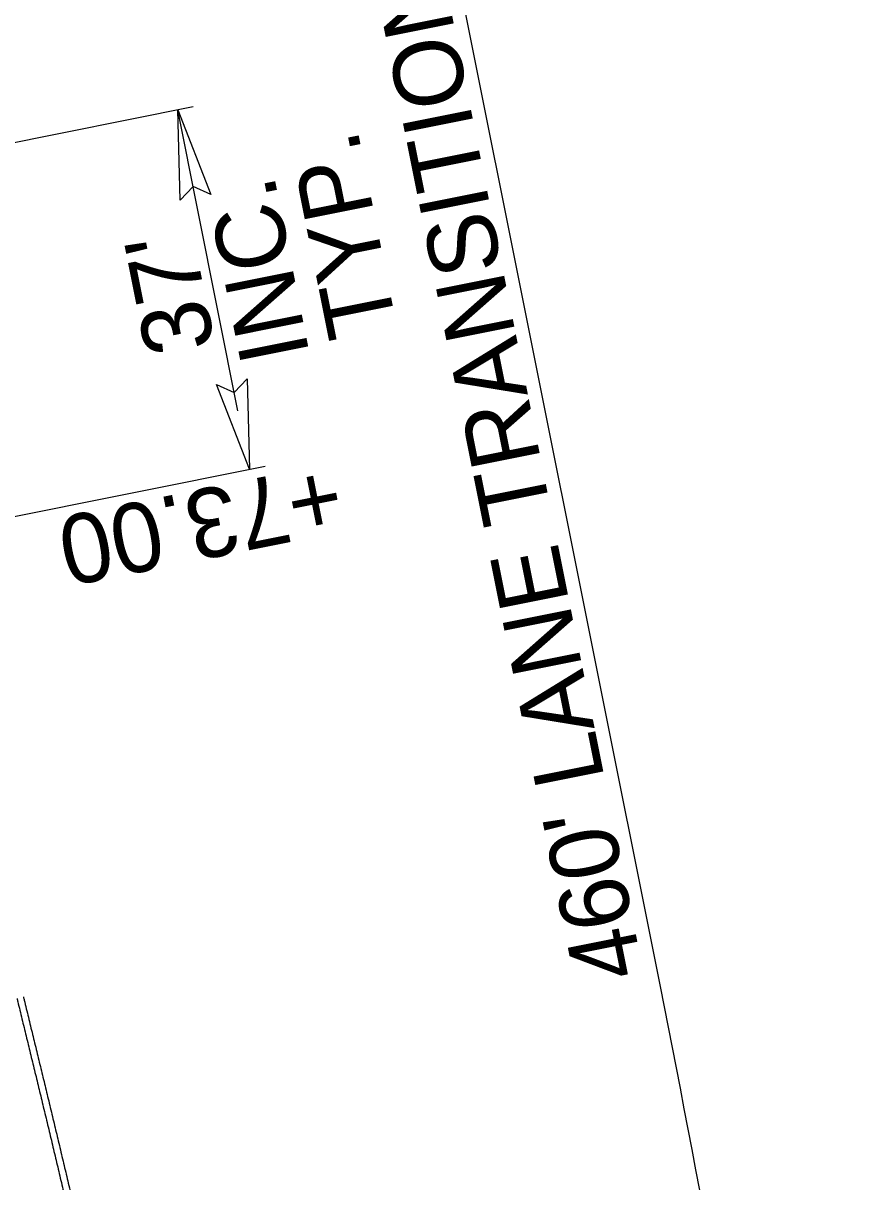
# Model space of a CAD drawing. Extents: x 1627861 to 1629601, y 761281 to 766239.
# Drawn here: x 1628396 to 1628480.7, y 765188 to 765304.9 of the extents above; entities that cross this region are included whole.
import ezdxf

# ---------------------------------------------------------------- set-up
doc = ezdxf.new("R2010")
doc.units = 0
for name, color, linetype in [('Exist Utilities Gas Meter Cogo Number', 7, 'Continuous'), ('Exist Utilities Power UG Cable SUE LOS B Cogo Point CELL', 7, 'Continuous'), ('Exist Utilities Telephone UG Cable SUE LOS B Cogo Number', 7, 'Continuous'), ('Scratch_Level_0', 7, 'Continuous')]:
    doc.layers.add(name, color=color, linetype=linetype)

msp = doc.modelspace()

# ---------------------------------------------------------------- linework, layer by layer
at = {"layer": 'Exist Utilities Gas Meter Cogo Number'}
for points in [[(1628411.87, 765287.06), (1628411.62, 765296.19), (1628414.97, 765287.63), (1628413.17, 765288.45)], [(1628418.64, 765269.04), (1628418.88, 765259.91), (1628415.54, 765268.47), (1628417.33, 765267.66)]]:
    msp.add_lwpolyline(points, close=True, dxfattribs=at)
at = {"layer": 'Exist Utilities Telephone UG Cable SUE LOS B Cogo Number'}
for points in [[(1628395.4, 765206.52), (1628395.48, 765206.18), (1628395.69, 765205.32), (1628395.9, 765204.45), (1628396.11, 765203.59)], [(1628396.05, 765206.67), (1628396.13, 765206.34), (1628396.34, 765205.47), (1628396.55, 765204.61), (1628396.76, 765203.75)], [(1628396.11, 765203.59), (1628396.32, 765202.73), (1628396.53, 765201.86), (1628396.74, 765201), (1628396.95, 765200.13), (1628397.16, 765199.27), (1628397.37, 765198.41), (1628397.58, 765197.54), (1628397.79, 765196.68), (1628398, 765195.79), (1628398.22, 765194.89), (1628398.44, 765194), (1628398.65, 765193.1), (1628398.87, 765192.2), (1628399.08, 765191.3), (1628399.29, 765190.41), (1628399.51, 765189.51), (1628399.72, 765188.61), (1628399.93, 765187.71), (1628400.14, 765186.82), (1628400.35, 765185.92), (1628400.56, 765185.02), (1628400.77, 765184.12), (1628400.98, 765183.22), (1628401.19, 765182.32), (1628401.39, 765181.43), (1628401.6, 765180.53), (1628401.81, 765179.63), (1628402.01, 765178.73), (1628402.22, 765177.83), (1628402.42, 765176.93), (1628402.63, 765176.03), (1628402.83, 765175.13), (1628403.03, 765174.23), (1628403.24, 765173.33), (1628403.44, 765172.43), (1628403.64, 765171.53), (1628403.84, 765170.63), (1628404.04, 765169.73), (1628404.24, 765168.82), (1628404.44, 765167.92), (1628404.64, 765167.02), (1628404.84, 765166.12), (1628405.03, 765165.22), (1628405.23, 765164.32), (1628405.43, 765163.41), (1628405.62, 765162.51), (1628405.82, 765161.61), (1628406.01, 765160.71), (1628406.2, 765159.81), (1628406.4, 765158.9), (1628406.59, 765158), (1628406.78, 765157.1), (1628406.97, 765156.19), (1628407.16, 765155.29), (1628407.35, 765154.39), (1628407.54, 765153.48), (1628407.73, 765152.58), (1628407.92, 765151.68), (1628408.11, 765150.77), (1628408.3, 765149.87), (1628408.48, 765148.96), (1628408.67, 765148.06), (1628408.85, 765147.15), (1628409.04, 765146.25), (1628409.22, 765145.34), (1628409.41, 765144.44), (1628409.59, 765143.53), (1628409.77, 765142.63), (1628409.96, 765141.72), (1628410.14, 765140.82), (1628410.32, 765139.91), (1628410.5, 765139.01), (1628410.68, 765138.1), (1628410.86, 765137.2)], [(1628396.76, 765203.75), (1628396.97, 765202.88), (1628397.18, 765202.02), (1628397.39, 765201.16), (1628397.6, 765200.29), (1628397.81, 765199.43), (1628398.02, 765198.56), (1628398.23, 765197.7), (1628398.44, 765196.83), (1628398.65, 765195.95), (1628398.87, 765195.05), (1628399.08, 765194.15), (1628399.3, 765193.25), (1628399.51, 765192.36), (1628399.73, 765191.46), (1628399.94, 765190.56), (1628400.15, 765189.66), (1628400.37, 765188.77), (1628400.58, 765187.87), (1628400.79, 765186.97), (1628401, 765186.07), (1628401.21, 765185.17), (1628401.42, 765184.27), (1628401.63, 765183.37), (1628401.84, 765182.47), (1628402.04, 765181.57), (1628402.25, 765180.68), (1628402.46, 765179.78), (1628402.66, 765178.88), (1628402.87, 765177.98), (1628403.07, 765177.08), (1628403.28, 765176.18), (1628403.48, 765175.28), (1628403.69, 765174.37), (1628403.89, 765173.47), (1628404.09, 765172.57), (1628404.29, 765171.67), (1628404.49, 765170.77), (1628404.69, 765169.87), (1628404.89, 765168.97), (1628405.09, 765168.07), (1628405.29, 765167.16), (1628405.49, 765166.26), (1628405.68, 765165.36), (1628405.88, 765164.46), (1628406.08, 765163.56), (1628406.27, 765162.65), (1628406.47, 765161.75), (1628406.66, 765160.85), (1628406.86, 765159.95), (1628407.05, 765159.04), (1628407.24, 765158.14), (1628407.43, 765157.24), (1628407.62, 765156.33), (1628407.82, 765155.43), (1628408.01, 765154.52), (1628408.2, 765153.62), (1628408.38, 765152.72), (1628408.57, 765151.81), (1628408.76, 765150.91), (1628408.95, 765150), (1628409.14, 765149.1), (1628409.32, 765148.19), (1628409.51, 765147.29), (1628409.69, 765146.38), (1628409.88, 765145.48), (1628410.06, 765144.57), (1628410.24, 765143.67), (1628410.43, 765142.76), (1628410.61, 765141.85), (1628410.79, 765140.95), (1628410.97, 765140.04), (1628411.15, 765139.14), (1628411.33, 765138.23), (1628411.51, 765137.33)]]:
    msp.add_spline(points, degree=3, dxfattribs=at)
at = {"layer": 'Scratch_Level_0'}
for p, q in [((1628460.34, 765207.73), (1628422.5, 765396.91)), ((1628357.62, 765285.39), (1628413.19, 765296.51)), ((1628417.7, 765265.8), (1628411.62, 765296.19)), ((1628366.27, 765249.39), (1628420.45, 765260.23))]:
    msp.add_line(p, q, dxfattribs=at)
msp.add_arc((1627004.18, 764916.47), 1485, 6.1376, 11.31093, dxfattribs=at)

# ---------------------------------------------------------------- texts
at = {"layer": 'Exist Utilities Power UG Cable SUE LOS B Cogo Point CELL'}
for s, p in [("460' LANE TRANSITION LT. & RT.", (1628458.65, 765209.05)), ('TYP.', (1628433.8, 765274.03)), ('INC.', (1628424.96, 765271.46)), ("37'", (1628415.42, 765272.34))]:
    msp.add_text(s, height=7, rotation=101.3109, dxfattribs=at).set_placement(p)
at = {"layer": 'Scratch_Level_0'}
msp.add_text('+73.00', height=7, rotation=191.3109, dxfattribs=at).set_placement((1628427.46, 765260.6))

doc.saveas('drawing.dxf')
